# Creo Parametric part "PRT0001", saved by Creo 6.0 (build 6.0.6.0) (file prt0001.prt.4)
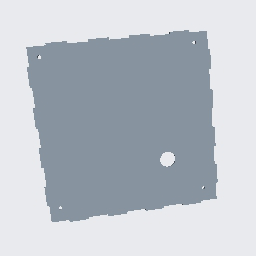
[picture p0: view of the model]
Units: Inch lbm Second (Pro/E Default); INCH, POUND, SECS

Created from: INLBS_PART_SOLID.PRT

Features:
  1. datum plane "RIGHT"
  2. datum plane "TOP"
  3. datum plane "FRONT"
  4. coordinate system
  5. sketch "Sketch 1"
  6. extrusion "Extrude 1"
  7. sketch "Sketch 2"
  8. extruded cut "Extrude 2"
  9. sketch "Sketch 3"
  10. extruded cut "Extrude 3"
  11. sketch "Sketch 4"
  12. extruded cut "Extrude 4"

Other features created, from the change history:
  extrusion "Extrude 2" (2 times)
  mirror "Mirror 1"

Surfaces: 70 plane, 5 cylinder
